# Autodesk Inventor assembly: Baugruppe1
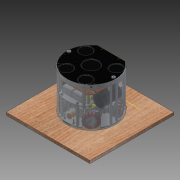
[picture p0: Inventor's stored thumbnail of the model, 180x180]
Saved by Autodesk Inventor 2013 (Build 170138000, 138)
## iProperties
Created: 2012-07
Part Number: Baugruppe1
Document SubType Name: Assembly
Designer: rYan
Author: rYan
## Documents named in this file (4)
- E:\Tigers SVN\mechanik\2013\Inventor\Demo mit Boden.iam
- E:\Tigers SVN\mechanik\2013\Inventor\Boden.ipt
- E:\Tigers SVN\mechanik\2013\Inventor\HBG-Roboter.iam
- E:\Tigers SVN\mechanik\2013\Inventor\Golfball.ipt
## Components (3 placed, 3 different names)
1. Boden:1 — Passend:3, Passend:4, Passend:5, Passend:6, Winkel:1, Tangential:1, Winkel:3, Passend:11
2. HBG-Roboter:1 [sub-assembly] — Winkel:3, Tangential:3, Passend:11
3. Golfball:1 — Tangential:1, Tangential:3
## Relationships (9: Mate 5, Angle 2, Tangent 2)
- Passend:3 [Mate]: Boden:1
- Passend:4 [Mate]: Boden:1
- Passend:5 [Mate]: Boden:1
- Passend:6 [Mate]: Boden:1
- Winkel:1 [Angle]: Boden:1
- Tangential:1: Boden:1 ↔ Golfball:1
- Winkel:3 [Angle]: Boden:1 ↔ HBG-Roboter:1
- Tangential:3: HBG-Roboter:1 ↔ Golfball:1
- Passend:11 [Mate]: Boden:1 ↔ HBG-Roboter:1
